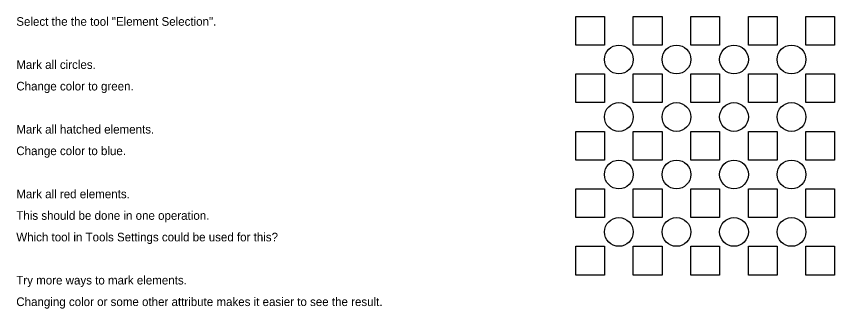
# Model space of a CAD drawing. Extents: x 1517706.2 to 1517734.6, y 6495365.8 to 6495376.
import ezdxf

# ---------------------------------------------------------------- set-up
doc = ezdxf.new("R2010")
doc.units = 0
doc.layers.add('Instruktioner', color=7, linetype='Continuous')
doc.layers.add('Lager 1', color=7, linetype='Continuous')

msp = doc.modelspace()

# ---------------------------------------------------------------- linework, layer by layer
at = {"layer": 'Lager 1'}
for points in [[(1517725.643, 6495375.967), (1517726.643, 6495375.967), (1517726.643, 6495374.967), (1517725.643, 6495374.967)], [(1517727.643, 6495375.967), (1517728.643, 6495375.967), (1517728.643, 6495374.967), (1517727.643, 6495374.967)], [(1517729.643, 6495375.967), (1517730.643, 6495375.967), (1517730.643, 6495374.967), (1517729.643, 6495374.967)], [(1517731.643, 6495375.967), (1517732.643, 6495375.967), (1517732.643, 6495374.967), (1517731.643, 6495374.967)], [(1517733.643, 6495375.967), (1517734.643, 6495375.967), (1517734.643, 6495374.967), (1517733.643, 6495374.967)], [(1517725.643, 6495373.967), (1517726.643, 6495373.967), (1517726.643, 6495372.967), (1517725.643, 6495372.967)], [(1517727.643, 6495373.967), (1517728.643, 6495373.967), (1517728.643, 6495372.967), (1517727.643, 6495372.967)], [(1517729.643, 6495373.967), (1517730.643, 6495373.967), (1517730.643, 6495372.967), (1517729.643, 6495372.967)], [(1517731.643, 6495373.967), (1517732.643, 6495373.967), (1517732.643, 6495372.967), (1517731.643, 6495372.967)], [(1517733.643, 6495373.967), (1517734.643, 6495373.967), (1517734.643, 6495372.967), (1517733.643, 6495372.967)], [(1517725.643, 6495371.967), (1517726.643, 6495371.967), (1517726.643, 6495370.967), (1517725.643, 6495370.967)], [(1517727.643, 6495371.967), (1517728.643, 6495371.967), (1517728.643, 6495370.967), (1517727.643, 6495370.967)], [(1517729.643, 6495371.967), (1517730.643, 6495371.967), (1517730.643, 6495370.967), (1517729.643, 6495370.967)], [(1517731.643, 6495371.967), (1517732.643, 6495371.967), (1517732.643, 6495370.967), (1517731.643, 6495370.967)], [(1517733.643, 6495371.967), (1517734.643, 6495371.967), (1517734.643, 6495370.967), (1517733.643, 6495370.967)], [(1517725.643, 6495369.967), (1517726.643, 6495369.967), (1517726.643, 6495368.967), (1517725.643, 6495368.967)], [(1517727.643, 6495369.967), (1517728.643, 6495369.967), (1517728.643, 6495368.967), (1517727.643, 6495368.967)], [(1517729.643, 6495369.967), (1517730.643, 6495369.967), (1517730.643, 6495368.967), (1517729.643, 6495368.967)], [(1517731.643, 6495369.967), (1517732.643, 6495369.967), (1517732.643, 6495368.967), (1517731.643, 6495368.967)], [(1517733.643, 6495369.967), (1517734.643, 6495369.967), (1517734.643, 6495368.967), (1517733.643, 6495368.967)], [(1517725.643, 6495367.967), (1517726.643, 6495367.967), (1517726.643, 6495366.967), (1517725.643, 6495366.967)], [(1517727.643, 6495367.967), (1517728.643, 6495367.967), (1517728.643, 6495366.967), (1517727.643, 6495366.967)], [(1517729.643, 6495367.967), (1517730.643, 6495367.967), (1517730.643, 6495366.967), (1517729.643, 6495366.967)], [(1517731.643, 6495367.967), (1517732.643, 6495367.967), (1517732.643, 6495366.967), (1517731.643, 6495366.967)], [(1517733.643, 6495367.967), (1517734.643, 6495367.967), (1517734.643, 6495366.967), (1517733.643, 6495366.967)]]:
    msp.add_lwpolyline(points, close=True, dxfattribs=at)
for centre in [(1517727.143, 6495374.467), (1517729.143, 6495374.467), (1517731.143, 6495374.467), (1517733.143, 6495374.467), (1517727.143, 6495372.467), (1517729.143, 6495372.467), (1517731.143, 6495372.467), (1517733.143, 6495372.467), (1517727.143, 6495370.467), (1517729.143, 6495370.467), (1517731.143, 6495370.467), (1517733.143, 6495370.467), (1517727.143, 6495368.467), (1517729.143, 6495368.467), (1517731.143, 6495368.467), (1517733.143, 6495368.467)]:
    msp.add_circle(centre, 0.5, dxfattribs=at)

# ---------------------------------------------------------------- texts
at = {"layer": 'Instruktioner'}
for s, p in [('Select the the tool "Element Selection".', (1517706.194, 6495375.639)), ('Mark all circles.', (1517706.194, 6495374.139)), ('Change color to green.', (1517706.194, 6495373.389)), ('Mark all hatched elements.', (1517706.194, 6495371.889)), ('Change color to blue.', (1517706.194, 6495371.139)), ('Mark all red elements.', (1517706.194, 6495369.639)), ('This should be done in one operation.', (1517706.194, 6495368.889)), ('Which tool in Tools Settings could be used for this?', (1517706.194, 6495368.139)), ('Try more ways to mark elements.', (1517706.194, 6495366.639)), ('Changing color or some other attribute makes it easier to see the result.', (1517706.194, 6495365.889))]:
    msp.add_text(s, height=0.3, dxfattribs=at).set_placement(p)

doc.saveas('drawing.dxf')
